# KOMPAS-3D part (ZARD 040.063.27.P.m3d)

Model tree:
1. Плоскость XY
2. Плоскость ZX
3. Плоскость ZY
4. Ось X
5. Ось Y
6. Ось Z
7. Начало координат
8. Булева операция:1
9. Булева операция:2
10. Булева операция:3
11. Булева операция:4
